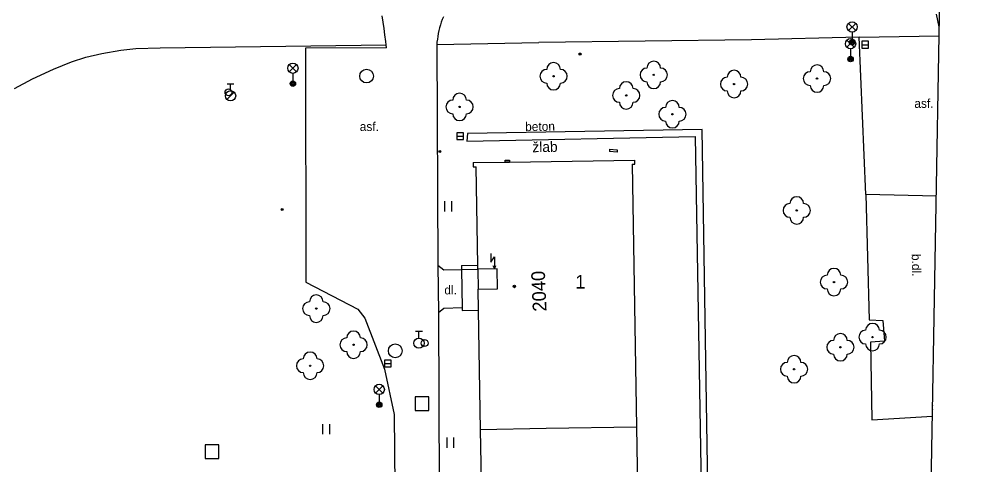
# Model space of a CAD drawing. Extents: x -641829 to -641525, y -1114855 to -1114359.
# Drawn here: x -641595.5 to -641525.3, y -1114568.4 to -1114535.8 of the extents above; entities that cross this region are included whole.
import ezdxf

# ---------------------------------------------------------------- set-up
doc = ezdxf.new("R2010")
doc.units = 0
for name, color, linetype in [('Vrstva 1', 7, 'Continuous'), ('Vrstva 10', 7, 'Continuous'), ('Vrstva 11', 7, 'Continuous'), ('Vrstva 20', 7, 'Continuous'), ('Vrstva 22', 7, 'Continuous'), ('Vrstva 24', 7, 'Continuous'), ('Vrstva 26', 7, 'Continuous'), ('Vrstva 27', 7, 'Continuous'), ('Vrstva 28', 7, 'Continuous'), ('Vrstva 33', 7, 'Continuous'), ('Vrstva 36', 7, 'Continuous'), ('Vrstva 39', 7, 'Continuous'), ('Vrstva 40', 7, 'Continuous'), ('Vrstva 42', 7, 'Continuous'), ('Vrstva 46', 7, 'Continuous'), ('Vrstva 47', 7, 'Continuous'), ('Vrstva 5', 7, 'Continuous')]:
    doc.layers.add(name, color=color, linetype=linetype)

msp = doc.modelspace()

# ---------------------------------------------------------------- linework, layer by layer
at = {"layer": 'Vrstva 1'}
msp.add_line((-641533.66, -1114832.21), (-641525.3, -1114362.64), dxfattribs=at)
at = {"layer": 'Vrstva 10'}
for p, q in [((-641568.97, -1114536.06), (-641569.05, -1114535.59)), ((-641564.66, -1114535.86), (-641564.73, -1114536.06)), ((-641564.58, -1114535.66), (-641564.66, -1114535.86)), ((-641528.4, -1114536.39), (-641528.61, -1114535.48)), ((-641568.9, -1114536.52), (-641568.97, -1114536.06)), ((-641568.84, -1114536.99), (-641568.9, -1114536.52)), ((-641564.91, -1114536.67), (-641564.95, -1114536.88)), ((-641564.86, -1114536.46), (-641564.91, -1114536.67)), ((-641564.8, -1114536.26), (-641564.86, -1114536.46)), ((-641564.73, -1114536.06), (-641564.8, -1114536.26)), ((-641528.394, -1114536.424), (-641528.4, -1114536.39)), ((-641568.78, -1114537.46), (-641568.84, -1114536.99)), ((-641565.02, -1114537.3), (-641565.05, -1114537.51)), ((-641564.99, -1114537.09), (-641565.02, -1114537.3)), ((-641564.95, -1114536.88), (-641564.99, -1114537.09)), ((-641534.24, -1114537.16), (-641528.405, -1114537.062)), ((-641533.76, -1114548.63), (-641534.24, -1114537.16)), ((-641568.73, -1114537.93), (-641574.65, -1114537.96)), ((-641574.65, -1114537.96), (-641574.61, -1114555.03)), ((-641565.05, -1114537.51), (-641565.06, -1114537.68)), ((-641565.06, -1114537.68), (-641564.98, -1114553.8)), ((-641528.613, -1114548.752), (-641533.76, -1114548.63)), ((-641564.98, -1114553.8), (-641564.94, -1114557.27)), ((-641574.61, -1114555.03), (-641570.82, -1114557.02)), ((-641570.82, -1114557.02), (-641570.31, -1114557.67)), ((-641570.31, -1114557.67), (-641568.87, -1114561.4)), ((-641564.94, -1114557.27), (-641564.87, -1114572.64)), ((-641568.87, -1114561.4), (-641568.18, -1114564.7)), ((-641568.18, -1114564.7), (-641568.01, -1114579.17))]:
    msp.add_line(p, q, dxfattribs=at)
msp.add_lwpolyline([(-641568.73, -1114537.93), (-641568.75, -1114537.71), (-641568.78, -1114537.46)], dxfattribs=at)
at = {"layer": 'Vrstva 11'}
for p, q in [((-641542.1, -1114537.35), (-641557.61, -1114537.55)), ((-641534.24, -1114537.16), (-641542.1, -1114537.35)), ((-641589.49, -1114538.33), (-641588.11, -1114538.09)), ((-641588.11, -1114538.09), (-641587.01, -1114537.98)), ((-641587.01, -1114537.98), (-641585.24, -1114537.93)), ((-641585.24, -1114537.93), (-641568.75, -1114537.71)), ((-641565.06, -1114537.68), (-641557.61, -1114537.55)), ((-641591.71, -1114538.95), (-641590.67, -1114538.62)), ((-641590.67, -1114538.62), (-641589.49, -1114538.33)), ((-641594.56, -1114540.18), (-641593.03, -1114539.48)), ((-641593.03, -1114539.48), (-641591.71, -1114538.95)), ((-641595.87, -1114540.89), (-641594.56, -1114540.18)), ((-641562.83, -1114544.18), (-641562.88, -1114544.73)), ((-641562.88, -1114544.73), (-641546.21, -1114544.41)), ((-641545.7, -1114543.89), (-641562.83, -1114544.18)), ((-641546.21, -1114544.41), (-641545.19, -1114602.86)), ((-641544.73, -1114603.5), (-641545.7, -1114543.89)), ((-641552.45, -1114545.33), (-641552.46, -1114545.5)), ((-641551.91, -1114545.54), (-641552.46, -1114545.5)), ((-641552.45, -1114545.33), (-641551.9, -1114545.37)), ((-641551.9, -1114545.37), (-641551.91, -1114545.54)), ((-641533.76, -1114548.63), (-641533.52, -1114557.79)), ((-641564.98, -1114553.8), (-641564.55, -1114554.13)), ((-641564.55, -1114554.13), (-641563.26, -1114554.11)), ((-641563.26, -1114553.81), (-641562.06, -1114553.79)), ((-641563.26, -1114553.81), (-641563.26, -1114554.11)), ((-641563.26, -1114554.11), (-641562.06, -1114554.09)), ((-641563.26, -1114554.11), (-641563.21, -1114556.91)), ((-641564.54, -1114556.95), (-641564.94, -1114557.27)), ((-641563.21, -1114556.91), (-641564.54, -1114556.95)), ((-641563.21, -1114556.91), (-641563.2, -1114557.11)), ((-641563.2, -1114557.11), (-641562.01, -1114557.09)), ((-641533.52, -1114557.79), (-641532.52, -1114557.84)), ((-641532.52, -1114557.84), (-641532.39, -1114559.34)), ((-641532.39, -1114559.34), (-641533.42, -1114559.42)), ((-641533.42, -1114559.42), (-641533.31, -1114565.08)), ((-641533.31, -1114565.08), (-641528.899, -1114564.813))]:
    msp.add_line(p, q, dxfattribs=at)
at = {"layer": 'Vrstva 20'}
for centre, radius in [((-641554.61, -1114538.38), 0.075), ((-641554.61, -1114538.38), 0.0204), ((-641564.84, -1114545.49), 0.075), ((-641564.84, -1114545.49), 0.0204), ((-641576.34, -1114549.73), 0.075), ((-641576.34, -1114549.73), 0.0204)]:
    msp.add_circle(centre, radius, dxfattribs=at)
at = {"layer": 'Vrstva 22'}
for centre in [(-641556.54, -1114540), (-641549.23, -1114539.9), (-641537.32, -1114540.17), (-641543.37, -1114540.57), (-641551.24, -1114541.4), (-641563.4, -1114542.24), (-641547.87, -1114542.78), (-641538.8, -1114549.8), (-641536.08, -1114555.03), (-641573.85, -1114556.97), (-641533.27, -1114559.05), (-641571.13, -1114559.61), (-641535.61, -1114559.79), (-641574.3, -1114561.14), (-641538.99, -1114561.39)]:
    msp.add_circle(centre, 0.05, dxfattribs=at)
for centre, start, end in [((-641557.04, -1114540), 90, 270), ((-641556.54, -1114539.5), 0, 180), ((-641556.04, -1114540), 270, 90), ((-641549.73, -1114539.9), 90, 270), ((-641549.23, -1114539.4), 0, 180), ((-641548.73, -1114539.9), 270, 90), ((-641543.37, -1114540.07), 0, 180), ((-641537.32, -1114539.67), 0, 180), ((-641543.87, -1114540.57), 90, 270), ((-641542.87, -1114540.57), 270, 90), ((-641537.82, -1114540.17), 90, 270), ((-641536.82, -1114540.17), 270, 90), ((-641556.54, -1114540.5), 180, 0), ((-641551.74, -1114541.4), 90, 270), ((-641551.24, -1114540.9), 0, 180), ((-641550.74, -1114541.4), 270, 90), ((-641549.23, -1114540.4), 180, 0), ((-641537.32, -1114540.67), 180, 0), ((-641563.4, -1114541.74), 0, 180), ((-641543.37, -1114541.07), 180, 0), ((-641563.9, -1114542.24), 90, 270), ((-641562.9, -1114542.24), 270, 90), ((-641551.24, -1114541.9), 180, 0), ((-641548.37, -1114542.78), 90, 270), ((-641547.87, -1114542.28), 0, 180), ((-641547.37, -1114542.78), 270, 90), ((-641563.4, -1114542.74), 180, 0), ((-641547.87, -1114543.28), 180, 0), ((-641539.3, -1114549.8), 90, 270), ((-641538.8, -1114549.3), 0, 180), ((-641538.3, -1114549.8), 270, 90), ((-641538.8, -1114550.3), 180, 0), ((-641536.08, -1114554.53), 0, 180), ((-641536.58, -1114555.03), 90, 270), ((-641535.58, -1114555.03), 270, 90), ((-641536.08, -1114555.53), 180, 0), ((-641573.85, -1114556.47), 0, 180), ((-641574.35, -1114556.97), 90, 270), ((-641573.35, -1114556.97), 270, 90), ((-641573.85, -1114557.47), 180, 0), ((-641533.27, -1114558.55), 0, 180), ((-641571.63, -1114559.61), 90, 270), ((-641571.13, -1114559.11), 0, 180), ((-641570.63, -1114559.61), 270, 90), ((-641535.61, -1114559.29), 0, 180), ((-641533.77, -1114559.05), 90, 270), ((-641532.77, -1114559.05), 270, 90), ((-641536.11, -1114559.79), 90, 270), ((-641535.11, -1114559.79), 270, 90), ((-641533.27, -1114559.55), 180, 0), ((-641574.3, -1114560.64), 0, 180), ((-641571.13, -1114560.11), 180, 0), ((-641538.99, -1114560.89), 0, 180), ((-641535.61, -1114560.29), 180, 0), ((-641574.8, -1114561.14), 90, 270), ((-641573.8, -1114561.14), 270, 90), ((-641539.49, -1114561.39), 90, 270), ((-641538.49, -1114561.39), 270, 90), ((-641574.3, -1114561.64), 180, 0), ((-641538.99, -1114561.89), 180, 0)]:
    msp.add_arc(centre, 0.5, start, end, dxfattribs=at)
at = {"layer": 'Vrstva 24'}
for p, q in [((-641561.11, -1114552.944), (-641561.11, -1114553.57)), ((-641561.11, -1114553.57), (-641560.86, -1114553.195)), ((-641560.86, -1114553.195), (-641560.86, -1114554.07)), ((-641560.97, -1114553.825), (-641560.86, -1114554.07)), ((-641560.86, -1114554.07), (-641560.75, -1114553.825))]:
    msp.add_line(p, q, dxfattribs=at)
msp.add_lwpolyline([(-641559.76, -1114546.12), (-641559.76, -1114546.27), (-641560.06, -1114546.27), (-641560.06, -1114546.13), (-641559.76, -1114546.12)], dxfattribs=at)
at = {"layer": 'Vrstva 26'}
for points in [[(-641566.63, -1114564.41), (-641565.63, -1114564.41), (-641565.63, -1114563.41), (-641566.63, -1114563.41)], [(-641581.97, -1114567.92), (-641580.97, -1114567.92), (-641580.97, -1114566.92), (-641581.97, -1114566.92)]]:
    msp.add_lwpolyline(points, close=True, dxfattribs=at)
at = {"layer": 'Vrstva 27'}
for p, q in [((-641534.06, -1114537.7), (-641533.56, -1114537.7)), ((-641563.6, -1114544.38), (-641563.1, -1114544.38)), ((-641568.88, -1114560.97), (-641568.38, -1114560.97))]:
    msp.add_line(p, q, dxfattribs=at)
for points in [[(-641534.06, -1114537.95), (-641533.56, -1114537.95), (-641533.56, -1114537.45), (-641534.06, -1114537.45)], [(-641563.6, -1114544.63), (-641563.1, -1114544.63), (-641563.1, -1114544.13), (-641563.6, -1114544.13)], [(-641568.88, -1114561.22), (-641568.38, -1114561.22), (-641568.38, -1114560.72), (-641568.88, -1114560.72)]]:
    msp.add_lwpolyline(points, close=True, dxfattribs=at)
for centre in [(-641570.18, -1114539.99), (-641568.09, -1114560.05)]:
    msp.add_circle(centre, 0.5, dxfattribs=at)
at = {"layer": 'Vrstva 28'}
for p, q in [((-641580.36, -1114540.554), (-641579.86, -1114540.554)), ((-641580.11, -1114541.054), (-641580.11, -1114540.554)), ((-641580.368, -1114541.702), (-641579.838, -1114541.172)), ((-641566.61, -1114558.614), (-641566.11, -1114558.614)), ((-641566.36, -1114559.114), (-641566.36, -1114558.614))]:
    msp.add_line(p, q, dxfattribs=at)
for centre, radius in [((-641580.26, -1114541.18), 0.25), ((-641580.11, -1114541.43), 0.375), ((-641566.36, -1114559.49), 0.375), ((-641565.95, -1114559.48), 0.25)]:
    msp.add_circle(centre, radius, dxfattribs=at)
at = {"layer": 'Vrstva 33'}
for p, q in [((-641535.024, -1114536.67), (-641534.496, -1114536.14)), ((-641535.024, -1114536.14), (-641534.496, -1114536.67)), ((-641535.134, -1114537.89), (-641534.606, -1114537.36)), ((-641535.134, -1114537.36), (-641534.606, -1114537.89)), ((-641534.76, -1114536.78), (-641534.76, -1114537.53)), ((-641534.87, -1114538), (-641534.87, -1114538.75)), ((-641575.825, -1114539.68), (-641575.295, -1114539.15)), ((-641575.825, -1114539.15), (-641575.295, -1114539.68)), ((-641575.56, -1114539.79), (-641575.56, -1114540.54)), ((-641569.525, -1114563.13), (-641568.995, -1114562.6)), ((-641569.525, -1114562.6), (-641568.995, -1114563.13)), ((-641569.26, -1114563.24), (-641569.26, -1114563.99)), ((-641528.892, -1114564.37), (-641528.886, -1114564.048))]:
    msp.add_line(p, q, dxfattribs=at)
for centre, radius in [((-641534.76, -1114536.405), 0.375), ((-641534.87, -1114537.625), 0.375), ((-641534.76, -1114537.53), 0.2), ((-641534.76, -1114537.53), 0.145), ((-641534.76, -1114537.53), 0.0876), ((-641534.87, -1114538.75), 0.2), ((-641534.87, -1114538.75), 0.145), ((-641534.87, -1114538.75), 0.0876), ((-641575.56, -1114539.415), 0.375), ((-641575.56, -1114540.54), 0.2), ((-641575.56, -1114540.54), 0.145), ((-641575.56, -1114540.54), 0.0876), ((-641569.26, -1114562.865), 0.375), ((-641569.26, -1114563.99), 0.2), ((-641569.26, -1114563.99), 0.145), ((-641569.26, -1114563.99), 0.0876)]:
    msp.add_circle(centre, radius, dxfattribs=at)
msp.add_arc((-641528.55, -1114564.215), 0.375, 153.5589, 204.40119, dxfattribs=at)
at = {"layer": 'Vrstva 36'}
for p, q in [((-641564.464, -1114549.884), (-641564.464, -1114549.132)), ((-641563.964, -1114549.884), (-641563.964, -1114549.132)), ((-641573.364, -1114566.142), (-641573.364, -1114565.394)), ((-641572.864, -1114566.142), (-641572.864, -1114565.394)), ((-641564.314, -1114567.132), (-641564.314, -1114566.384)), ((-641563.814, -1114567.132), (-641563.814, -1114566.384))]:
    msp.add_line(p, q, dxfattribs=at)
at = {"layer": 'Vrstva 39'}
for radius in [0.09, 0.0398]:
    msp.add_circle((-641559.4, -1114555.35), radius, dxfattribs=at)
at = {"layer": 'Vrstva 5'}
for p, q in [((-641562.41, -1114546.31), (-641562.4, -1114546.61)), ((-641550.81, -1114546.42), (-641550.61, -1114546.42)), ((-641550.81, -1114546.42), (-641550.49, -1114565.62)), ((-641550.61, -1114546.42), (-641550.61, -1114546.12)), ((-641562.4, -1114546.61), (-641562.18, -1114546.61)), ((-641560.66, -1114554.07), (-641562.06, -1114554.09)), ((-641562.06, -1114554.09), (-641562.04, -1114555.54)), ((-641560.64, -1114555.52), (-641560.66, -1114554.07)), ((-641562.04, -1114555.54), (-641560.64, -1114555.52)), ((-641557.09, -1114565.73), (-641561.86, -1114565.81)), ((-641550.49, -1114565.62), (-641557.09, -1114565.73)), ((-641550.49, -1114565.62), (-641550.21, -1114583.11))]:
    msp.add_line(p, q, dxfattribs=at)
for points in [[(-641562.41, -1114546.31), (-641560.06, -1114546.27), (-641559.76, -1114546.27), (-641550.61, -1114546.12)], [(-641562.06, -1114554.09), (-641562.06, -1114553.79), (-641562.18, -1114546.61)], [(-641561.86, -1114565.81), (-641562.01, -1114557.09), (-641562.04, -1114555.54)], [(-641561.72, -1114573.6), (-641561.73, -1114573.3), (-641561.86, -1114565.81)]]:
    msp.add_lwpolyline(points, dxfattribs=at)

# ---------------------------------------------------------------- texts
at = {"layer": 'Vrstva 40'}
for s, p in [('asf.', (-641530.22, -1114542.31)), ('asf.', (-641570.68, -1114544)), ('dl.', (-641564.51, -1114555.93))]:
    msp.add_text(s, height=0.65, dxfattribs=at).set_placement(p)
for s, height, rotation, p in [('beton', 0.6499, 0.96989, (-641558.61, -1114544.01)), ('b.dl.', 0.65, 271.15349, (-641530.41, -1114552.98))]:
    msp.add_text(s, height=height, rotation=rotation, dxfattribs=at).set_placement(p)
at = {"layer": 'Vrstva 42'}
msp.add_text('žlab', height=0.7499, rotation=0.96989, dxfattribs=at).set_placement((-641558.08, -1114545.55))
at = {"layer": 'Vrstva 46'}
msp.add_text('1', height=1, dxfattribs=at).set_placement((-641554.96, -1114555.51))
at = {"layer": 'Vrstva 47'}
msp.add_text('2040', height=1, rotation=92.53517, dxfattribs=at).set_placement((-641557.05, -1114557.16))

doc.saveas('drawing.dxf')
